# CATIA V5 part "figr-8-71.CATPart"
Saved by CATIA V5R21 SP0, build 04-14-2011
Part number: Part1
Bounding box of the stored display mesh (mm): x -81.893 to 81.893, y -175.508 to 175.508, z -150 to 146
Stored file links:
  D:\CATIA V5R21 E-RESOURCES\CATIA-V5R21\catia-v5r21-prt\c08-catia-v5r20-prt\c08-catia-v5r21-figr-8-71.CATPart
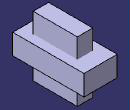
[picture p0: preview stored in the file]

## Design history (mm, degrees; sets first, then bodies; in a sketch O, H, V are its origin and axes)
Body1 (main body)
  Sketch1 on xy-plane, origin (0, 0, 0), H (1, 0, 0), V (0, 1, 0)
    line L1 (-81.8929, 175.5076) -> (81.8929, 175.5076)
    line L2 (81.8929, 175.5076) -> (81.8929, -175.5076)
    line L3 (81.8929, -175.5076) -> (-81.8929, -175.5076)
    line L4 (-81.8929, -175.5076) -> (-81.8929, 175.5076)
    axis line L5 (81.8929, -175.5076) -> (-81.8929, 175.5076)
    horizontal: L1 H, L3 H
    vertical: L2 V, L4 V
    midpoint: O L5
  Pad1: profile Sketch1, direction (0, 0, 1), length 50, mirrored extent
Body2
  Sketch2 on xy-plane, origin (0, 0, 0), H (1, 0, 0), V (0, 1, 0)
    line L1 (-37.4906, 99.3013) -> (38.4681, 99.3013)
    line L2 (38.4681, 99.3013) -> (38.4681, -118.5305)
    line L3 (38.4681, -118.5305) -> (-37.4906, -118.5305)
    line L4 (-37.4906, -118.5305) -> (-37.4906, 99.3013)
    horizontal: L1 H, L3 H
    vertical: L2 V, L4 V
  Pad2: profile Sketch2, direction (0, 0, 1), length 146, opposite side length 150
